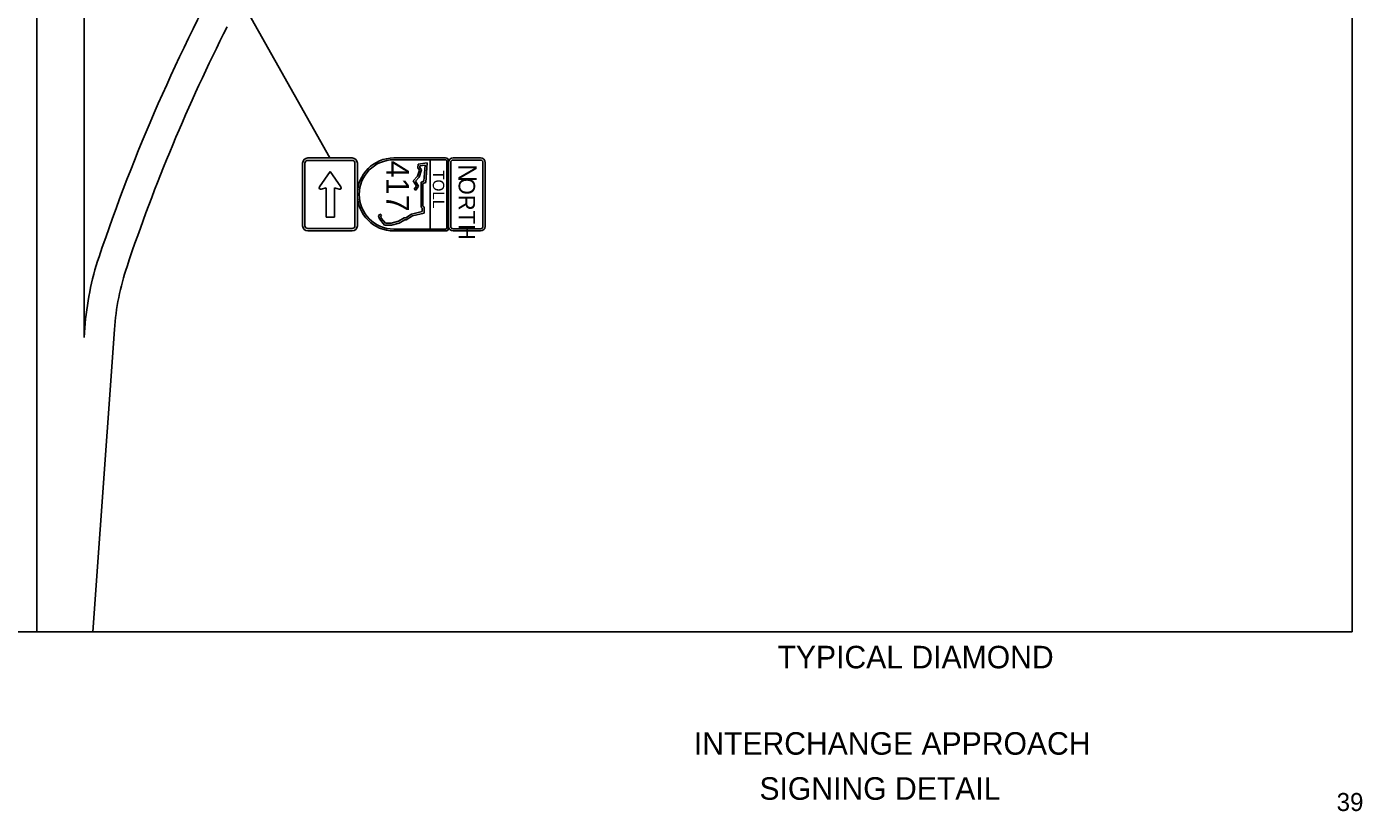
# Model space of a CAD drawing. Extents: x -830008.4 to -829992.7, y 1290284.1 to 1290294.4.
# Drawn here: x -830000.13 to -829992.72, y 1290284.33 to 1290288.68 of the extents above; entities that cross this region are included whole.
import ezdxf

# ---------------------------------------------------------------- set-up
doc = ezdxf.new("R2010")
doc.units = 0
for name, color, linetype in [('NonPlottingEle_dp', 7, 'Continuous'), ('SignPanel', 7, 'Continuous'), ('TextLabel', 7, 'Continuous'), ('TextMisc', 7, 'Continuous'), ('TextShtNo', 7, 'Continuous')]:
    doc.layers.add(name, color=color, linetype=linetype)

msp = doc.modelspace()

# ---------------------------------------------------------------- linework, layer by layer
at = {"layer": 'NonPlottingEle_dp'}
msp.add_lwpolyline([(-830007.4742, 1290294.228), (-829992.7742, 1290294.228), (-829992.7742, 1290285.328), (-830007.4742, 1290285.328)], close=True, dxfattribs=at)
at = {"layer": 'SignPanel'}
for p, q in [((-829997.9584, 1290287.901), (-829997.9558, 1290287.9219)), ((-829997.9494, 1290287.8895), (-829997.9584, 1290287.901)), ((-829997.9558, 1290287.9219), (-829997.9058, 1290287.9297)), ((-829997.9463, 1290287.9127), (-829997.9474, 1290287.9041)), ((-829997.9474, 1290287.9041), (-829997.9376, 1290287.8916)), ((-829997.9173, 1290287.9173), (-829997.9463, 1290287.9127)), ((-829997.9242, 1290287.8278), (-829997.9173, 1290287.9173)), ((-829997.9058, 1290287.9297), (-829997.9142, 1290287.8204)), ((-829998.4442, 1290287.8823), (-829998.5034, 1290287.796)), ((-829998.385, 1290287.796), (-829998.4442, 1290287.8823)), ((-829997.9836, 1290287.8302), (-829997.9606, 1290287.8549)), ((-829997.9665, 1290287.8011), (-829997.9836, 1290287.8302)), ((-829997.9513, 1290287.8495), (-829997.9705, 1290287.8287)), ((-829997.9705, 1290287.8287), (-829997.954, 1290287.8007)), ((-829997.9606, 1290287.8549), (-829997.9494, 1290287.8895)), ((-829997.9376, 1290287.8916), (-829997.9513, 1290287.8495)), ((-829997.9405, 1290287.8215), (-829997.9242, 1290287.8278)), ((-829997.9405, 1290287.6832), (-829997.9405, 1290287.8215)), ((-829997.9142, 1290287.8204), (-829997.9299, 1290287.8142)), ((-829998.4938, 1290287.7828), (-829998.467, 1290287.7908)), ((-829998.467, 1290287.7908), (-829998.467, 1290287.6284)), ((-829998.4214, 1290287.6284), (-829998.4214, 1290287.7908)), ((-829998.4214, 1290287.7908), (-829998.3946, 1290287.7828)), ((-829997.9782, 1290287.7837), (-829997.9665, 1290287.8011)), ((-829997.9695, 1290287.7778), (-829997.9782, 1290287.7837)), ((-829997.954, 1290287.8007), (-829997.9695, 1290287.7778)), ((-829997.9299, 1290287.8142), (-829997.9299, 1290287.6888)), ((-829997.9335, 1290287.6785), (-829997.9405, 1290287.6832)), ((-829997.9335, 1290287.6587), (-829997.9335, 1290287.6785)), ((-829997.9299, 1290287.6888), (-829997.923, 1290287.6841)), ((-829997.923, 1290287.6841), (-829997.923, 1290287.6503)), ((-829998.467, 1290287.6284), (-829998.4214, 1290287.6284)), ((-829998.1758, 1290287.6348), (-829998.1686, 1290287.6452)), ((-829998.1718, 1290287.6184), (-829998.1758, 1290287.6348)), ((-829998.1435, 1290287.5839), (-829998.1718, 1290287.6184)), ((-829998.1686, 1290287.6452), (-829998.1599, 1290287.6392)), ((-829998.1599, 1290287.6392), (-829998.1644, 1290287.6327)), ((-829998.1644, 1290287.6327), (-829998.1622, 1290287.6232)), ((-829998.1622, 1290287.6232), (-829998.1385, 1290287.5944)), ((-829998.1053, 1290287.5944), (-829998.0658, 1290287.6052)), ((-829998.0658, 1290287.6052), (-829998.0335, 1290287.6248)), ((-829998.0306, 1290287.6143), (-829998.0615, 1290287.5954)), ((-829998.0335, 1290287.6248), (-829998.0251, 1290287.6248)), ((-829998.0221, 1290287.6143), (-829998.0306, 1290287.6143)), ((-829998.0251, 1290287.6248), (-829997.9928, 1290287.6449)), ((-829997.9887, 1290287.6351), (-829998.0221, 1290287.6143)), ((-829997.9928, 1290287.6449), (-829997.9335, 1290287.6587)), ((-829997.923, 1290287.6503), (-829997.9887, 1290287.6351)), ((-829998.1039, 1290287.5839), (-829998.1435, 1290287.5839)), ((-829998.1385, 1290287.5944), (-829998.1053, 1290287.5944)), ((-829998.0615, 1290287.5954), (-829998.1039, 1290287.5839))]:
    msp.add_line(p, q, dxfattribs=at)
for points in [[(-829998.5977, 1290287.5807), (-829998.5977, 1290287.9278)], [(-829998.5844, 1290287.5807), (-829998.5844, 1290287.9278)], [(-829998.5687, 1290287.9567), (-829998.3228, 1290287.9567)], [(-829998.5687, 1290287.9435), (-829998.3228, 1290287.9435)], [(-829998.3072, 1290287.9278), (-829998.3072, 1290287.5807)], [(-829998.2939, 1290287.9278), (-829998.2939, 1290287.5807)], [(-829998.0914, 1290287.9567), (-829997.8045, 1290287.9567)], [(-829998.0914, 1290287.9466), (-829997.8045, 1290287.9466)], [(-829997.8889, 1290287.9466), (-829997.8889, 1290287.5619)], [(-829997.7978, 1290287.9399), (-829997.7978, 1290287.5686)], [(-829997.7877, 1290287.9399), (-829997.7877, 1290287.5686)], [(-829997.7877, 1290287.577), (-829997.7877, 1290287.9314)], [(-829997.776, 1290287.577), (-829997.776, 1290287.9314)], [(-829997.7623, 1290287.9567), (-829997.6105, 1290287.9567)], [(-829997.7623, 1290287.9451), (-829997.6105, 1290287.9451)], [(-829997.5968, 1290287.9314), (-829997.5968, 1290287.577)], [(-829997.5852, 1290287.9314), (-829997.5852, 1290287.577)], [(-829998.3228, 1290287.565), (-829998.5687, 1290287.565)], [(-829998.3228, 1290287.5517), (-829998.5687, 1290287.5517)], [(-829997.8045, 1290287.5619), (-829998.0914, 1290287.5619)], [(-829997.8045, 1290287.5517), (-829998.0914, 1290287.5517)], [(-829997.6105, 1290287.5633), (-829997.7623, 1290287.5633)], [(-829997.6105, 1290287.5517), (-829997.7623, 1290287.5517)]]:
    msp.add_lwpolyline(points, dxfattribs=at)
for centre, radius, start, end in [((-829998.5687, 1290287.9278), 0.0289, 90, 180), ((-829998.5687, 1290287.9278), 0.0157, 90, 180), ((-829998.3228, 1290287.9278), 0.0289, 360, 90), ((-829998.3228, 1290287.9278), 0.0157, 360, 89.9456), ((-829998.0914, 1290287.7542), 0.2025, 90, 270), ((-829998.0914, 1290287.7542), 0.1924, 90, 270), ((-829997.8045, 1290287.9399), 0.0169, 0, 90), ((-829997.8045, 1290287.9399), 0.00675, 0, 90), ((-829997.7623, 1290287.9314), 0.0253, 90, 180), ((-829997.7623, 1290287.9314), 0.0137, 90, 180), ((-829997.6105, 1290287.9314), 0.0253, 0, 90), ((-829997.6105, 1290287.9314), 0.0137, 0, 90), ((-829998.4963, 1290287.7911), 0.00868, 145.51192, 286.64431), ((-829998.3921, 1290287.7911), 0.00868, 253.35571, 34.48807), ((-829998.5687, 1290287.5807), 0.0289, 180, 270), ((-829998.5687, 1290287.5807), 0.0157, 180, 270), ((-829998.3228, 1290287.5807), 0.0289, 270, 360), ((-829998.3228, 1290287.5807), 0.0157, 270.0544, 360), ((-829997.8045, 1290287.5686), 0.0169, 270, 0), ((-829997.8045, 1290287.5686), 0.00675, 270, 0), ((-829997.7623, 1290287.577), 0.0253, 180, 270), ((-829997.7623, 1290287.577), 0.0137, 180, 270), ((-829997.6105, 1290287.577), 0.0253, 270, 0), ((-829997.6105, 1290287.577), 0.0137, 270, 0)]:
    msp.add_arc(centre, radius, start, end, dxfattribs=at)
at = {"layer": 'TextLabel'}
for p, q in [((-830000.0719, 1290294.228), (-830000.0719, 1290285.328)), ((-829999.2537, 1290289.3928), (-829998.4458, 1290287.9567)), ((-829999.8091, 1290288.9868), (-829999.8096, 1290286.9607)), ((-829999.8056, 1290287.0168), (-829999.8096, 1290286.9607)), ((-829999.642, 1290287.0051), (-829999.7619, 1290285.328))]:
    msp.add_line(p, q, dxfattribs=at)
for centre, radius, start, end in [((-829990.0742, 1290284.1655), 10.183, 151.15873, 161.43615), ((-829990.0742, 1290284.1655), 10.0189, 153.18648, 161.43615), ((-829998.2289, 1290286.9041), 1.5807, 161.43615, 176.0167), ((-829998.2289, 1290286.9041), 1.4167, 161.43615, 175.91011)]:
    msp.add_arc(centre, radius, start, end, dxfattribs=at)

# ---------------------------------------------------------------- texts
at = {"layer": 'SignPanel'}
for s, height, p in [('417', 0.12656, (-829998.1336, 1290287.9416)), ('N', 0.1013, (-829997.733, 1290287.9212)), ('TOLL', 0.06328, (-829997.875, 1290287.8887)), ('ORTH', 0.09113, (-829997.7318, 1290287.8473))]:
    msp.add_text(s, height=height, rotation=270, dxfattribs=at).set_placement(p)
at = {"layer": 'TextMisc'}
for s, p in [('TYPICAL DIAMOND', (-829995.9625, 1290285.1249)), ('  INTERCHANGE APPROACH  ', (-829996.5194, 1290284.6457)), ('     SIGNING DETAIL     ', (-829996.2949, 1290284.3957))]:
    msp.add_text(s, height=0.125, dxfattribs=at).set_placement(p)
at = {"layer": 'TextShtNo'}
msp.add_text('39', height=0.1, dxfattribs=at).set_placement((-829992.8599, 1290284.3332))

doc.saveas('drawing.dxf')
